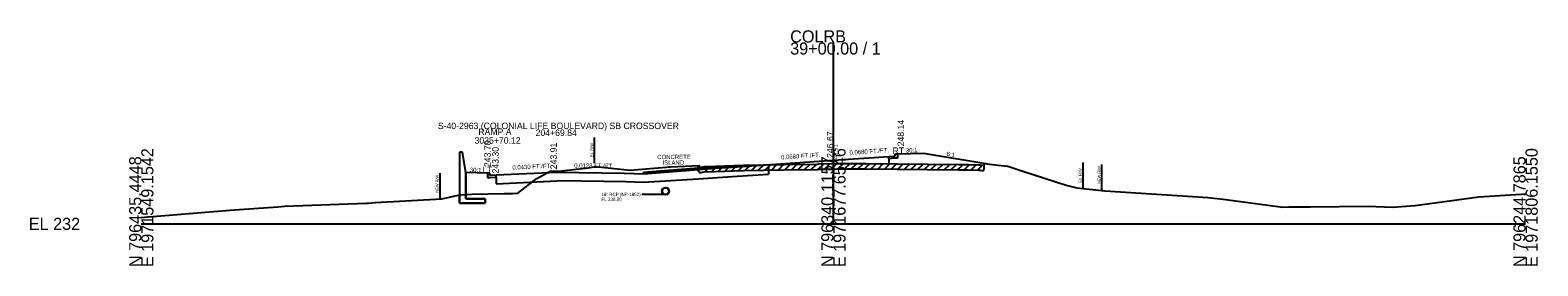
# Model space of a CAD drawing. Extents: x -26 to 1971766, y -10 to 796432.
# Drawn here: x -25.7 to 322.8, y 3490.3 to 3544.7 of the extents above; entities that cross this region are included whole.
import ezdxf

# ---------------------------------------------------------------- set-up
doc = ezdxf.new("R2010")
doc.units = 0
for name, color, linetype in [('BR_AUTO DIMENSION', 7, 'Continuous'), ('BR_BORDER LINES', 7, 'Continuous'), ('BR_CENTER LINE BASELINE', 7, 'Continuous'), ('BR_CONCRETE', 7, 'Continuous'), ('BR_DETAILS', 7, 'Continuous'), ('BR_PRESTRESSED BEAM', 7, 'Continuous'), ('BR_REBAR', 7, 'Continuous'), ('BR_TABLE LINES', 7, 'Continuous'), ('Default', 7, 'Continuous'), ('Level 31', 7, 'Continuous'), ('MISCELLANEOUS', 7, 'Continuous'), ('North Arrow', 7, 'Continuous'), ('RD_EX_Conc', 7, 'Continuous'), ('RD_EX_Road', 7, 'Continuous'), ('RD_HC_CL_Rel', 7, 'Continuous'), ('RD_PD_ALT2_TnTmp', 7, 'Continuous'), ('RD_PD_CstnLmt', 7, 'Continuous'), ('RD_PD_Final_LnLine', 7, 'Continuous'), ('RD_PD_Final_TrvlWay', 7, 'Continuous'), ('RD_PD_FOC', 7, 'Continuous'), ('RD_PD_MedBWall', 7, 'Continuous'), ('RD_PD_WallFill', 7, 'Continuous'), ('RD_SHT_IplotShp', 7, 'Continuous')]:
    doc.layers.add(name, color=color, linetype=linetype)

msp = doc.modelspace()

# ---------------------------------------------------------------- linework, layer by layer
at = {"layer": 'BR_AUTO DIMENSION'}
for p, q in [((160, 3500), (160, 3541.89)), ((0, 3500), (160, 3500)), ((160, 3500), (320, 3500))]:
    msp.add_line(p, q, dxfattribs=at)
at = {"layer": 'BR_BORDER LINES'}
msp.add_lwpolyline([(0, 3501.48), (1.51, 3501.6), (2.69, 3501.69), (20.49, 3503.18), (31.58, 3503.94), (33.11, 3504.06), (37.34, 3504.26), (52.05, 3504.8), (52.51, 3504.81), (54.04, 3504.9), (69.48, 3505.79), (72.25, 3506.42), (73.28, 3506.64), (73.59, 3506.68), (76.43, 3506.85), (83.89, 3507.03), (85.79, 3507.04), (87.02, 3507.11), (91.43, 3510.51), (94.55, 3512.13), (97.11, 3512.22), (103.34, 3512.97), (104.72, 3513.19), (105.7, 3513.13), (112.99, 3512.37), (121.3, 3513.12), (121.97, 3513.17), (122.37, 3513.18), (128.97, 3513.44), (129.07, 3513.04), (130.08, 3513.24), (132.75, 3513.34), (139.22, 3513.57), (148.63, 3513.7), (156.3, 3513.81), (156.6, 3513.87), (160, 3513.91), (161.43, 3513.92), (167.06, 3513.96), (167.58, 3513.94), (174.7, 3513.87), (181.71, 3513.8), (189.02, 3513.72), (190.37, 3513.71), (191.16, 3513.69), (193.57, 3513.65), (193.9, 3513.61), (194.7, 3513.5), (194.8, 3513.9), (198.77, 3513.48), (200.33, 3513.31), (203.78, 3512.2), (213.78, 3508.95), (216.24, 3508.3), (222.73, 3507.6), (240.69, 3506.49), (246.55, 3506.09), (250.08, 3505.69), (263.86, 3503.85), (265.31, 3503.91), (270.31, 3503.95), (283.62, 3504.05), (289.23, 3503.88), (294.46, 3504.21), (309.22, 3506.27), (318.95, 3506.84), (320, 3506.91)], dxfattribs=at)
at = {"layer": 'BR_CENTER LINE BASELINE'}
for p, q in [((128.75, 3512.18), (128.75, 3513.43)), ((194.79, 3513.84), (194.79, 3512.59)), ((128.75, 3512.18), (128.97, 3512.19)), ((128.97, 3512.19), (129.07, 3511.79)), ((129.07, 3511.79), (130.08, 3511.99)), ((130.08, 3511.99), (132.75, 3512.09)), ((132.75, 3512.09), (139.22, 3512.32)), ((139.22, 3512.32), (148.63, 3512.45)), ((148.63, 3512.45), (156.3, 3512.56)), ((156.3, 3512.56), (156.6, 3512.62)), ((156.6, 3512.62), (160, 3512.66)), ((160, 3512.66), (161.43, 3512.67)), ((161.43, 3512.67), (167.06, 3512.71)), ((167.06, 3512.71), (167.58, 3512.69)), ((167.58, 3512.69), (174.7, 3512.62)), ((174.7, 3512.62), (181.71, 3512.55)), ((181.71, 3512.55), (189.02, 3512.47)), ((189.02, 3512.47), (190.37, 3512.46)), ((190.37, 3512.46), (191.16, 3512.44)), ((191.16, 3512.44), (193.57, 3512.4)), ((193.57, 3512.4), (193.9, 3512.36)), ((193.9, 3512.36), (194.7, 3512.25)), ((194.7, 3512.25), (194.79, 3512.59))]:
    msp.add_line(p, q, dxfattribs=at)
at = {"layer": 'BR_DETAILS'}
for p, q in [((74.28, 3516.53), (73.53, 3516.53)), ((73.53, 3516.53), (73.53, 3504.75)), ((75.03, 3511.86), (74.28, 3516.53)), ((133.69, 3513.23), (116.06, 3511.86)), ((133.69, 3512.9), (133.69, 3513.23)), ((75.03, 3505.76), (75.03, 3511.86)), ((116.06, 3511.53), (133.69, 3512.9)), ((116.06, 3511.53), (116.06, 3511.86)), ((73.53, 3504.75), (75.03, 3504.75)), ((79.53, 3505.76), (75.03, 3505.76)), ((75.03, 3504.75), (79.53, 3504.76)), ((79.53, 3504.76), (79.53, 3505.76))]:
    msp.add_line(p, q, dxfattribs=at)
at = {"layer": 'BR_PRESTRESSED BEAM'}
for p, q in [((174.23, 3515.14), (172.81, 3515.05)), ((174.82, 3515.14), (174.23, 3515.14)), ((174.82, 3516.14), (174.82, 3515.14)), ((80.02, 3511.7), (80.02, 3510.7)), ((80.02, 3511.7), (80.02, 3510.7)), ((80.02, 3510.7), (80.61, 3510.7)), ((80.61, 3510.7), (82.03, 3510.78))]:
    msp.add_line(p, q, dxfattribs=at)
at = {"layer": 'BR_TABLE LINES'}
for p, q in [((104.72, 3519.98), (104.72, 3513.98)), ((217.62, 3514.16), (217.62, 3508.16))]:
    msp.add_line(p, q, dxfattribs=at)
at = {"layer": 'Level 31'}
for p, q in [((130.28, 3512), (131.61, 3513.29)), ((131.82, 3512.05), (133.15, 3513.35)), ((133.36, 3512.11), (134.69, 3513.41)), ((134.9, 3512.16), (136.23, 3513.46)), ((136.43, 3512.22), (137.76, 3513.52)), ((137.97, 3512.28), (139.3, 3513.57)), ((139.51, 3512.33), (140.81, 3513.59)), ((141.04, 3512.35), (142.34, 3513.62)), ((142.58, 3512.37), (143.88, 3513.64)), ((144.12, 3512.39), (145.42, 3513.66)), ((145.65, 3512.41), (146.95, 3513.68)), ((147.19, 3512.43), (148.49, 3513.7)), ((148.73, 3512.45), (150.03, 3513.72)), ((150.27, 3512.48), (151.57, 3513.74)), ((151.8, 3512.5), (153.1, 3513.77)), ((153.34, 3512.52), (154.64, 3513.79)), ((154.88, 3512.54), (156.18, 3513.81)), ((156.41, 3512.58), (157.75, 3513.88)), ((157.95, 3512.64), (159.24, 3513.9)), ((159.49, 3512.65), (160.78, 3513.91)), ((161.03, 3512.67), (162.32, 3513.93)), ((162.56, 3512.68), (163.85, 3513.94)), ((164.1, 3512.69), (165.39, 3513.95)), ((165.64, 3512.7), (166.93, 3513.96)), ((167.17, 3512.71), (168.43, 3513.93)), ((168.71, 3512.68), (169.98, 3513.91)), ((170.25, 3512.66), (171.52, 3513.9)), ((171.78, 3512.65), (173.05, 3513.89)), ((173.32, 3512.63), (174.59, 3513.87)), ((174.86, 3512.62), (176.13, 3513.86)), ((176.4, 3512.6), (177.66, 3513.84)), ((177.93, 3512.59), (179.2, 3513.82)), ((179.47, 3512.57), (180.74, 3513.81)), ((181.01, 3512.55), (182.27, 3513.79)), ((182.54, 3512.54), (183.81, 3513.78)), ((184.08, 3512.52), (185.35, 3513.76)), ((185.62, 3512.51), (186.89, 3513.74)), ((187.16, 3512.49), (188.42, 3513.73)), ((188.69, 3512.48), (189.96, 3513.71)), ((190.23, 3512.46), (191.48, 3513.68)), ((191.77, 3512.43), (193.03, 3513.66)), ((193.3, 3512.41), (194.46, 3513.54)), ((128.75, 3512.18), (129.76, 3513.18))]:
    msp.add_line(p, q, dxfattribs=at)
at = {"layer": 'MISCELLANEOUS'}
for p, q in [((144.96, 3513.65), (148.63, 3513.7)), ((148.63, 3513.7), (156.3, 3513.81)), ((156.3, 3513.81), (156.6, 3513.87)), ((156.6, 3513.87), (160, 3513.91)), ((160, 3513.91), (161.43, 3513.92)), ((161.43, 3513.92), (167.06, 3513.96)), ((167.06, 3513.96), (167.58, 3513.94)), ((167.58, 3513.94), (172.81, 3513.89))]:
    msp.add_line(p, q, dxfattribs=at)
at = {"layer": 'North Arrow'}
for p, q in [((137.72, 3513.16), (160, 3514.67)), ((160, 3514.67), (172.81, 3515.55)), ((82.03, 3511.3), (96.07, 3511.91)), ((96.07, 3511.91), (111.61, 3511.71))]:
    msp.add_line(p, q, dxfattribs=at)
at = {"layer": 'RD_EX_Conc'}
for p, q in [((172.81, 3515.55), (174.23, 3515.64)), ((172.81, 3515.57), (172.81, 3515.55)), ((174.23, 3515.64), (174.32, 3516.14)), ((174.32, 3516.14), (174.82, 3516.14)), ((80.52, 3511.7), (80.02, 3511.7)), ((80.52, 3511.7), (80.02, 3511.7)), ((80.61, 3511.2), (80.52, 3511.7)), ((80.61, 3511.2), (80.52, 3511.7)), ((82.03, 3511.28), (80.61, 3511.2)), ((82.03, 3511.3), (82.03, 3511.28))]:
    msp.add_line(p, q, dxfattribs=at)
at = {"layer": 'RD_EX_Road'}
for p, q in [((144.96, 3513.65), (144.96, 3511.49)), ((172.81, 3515.55), (172.81, 3515.57)), ((172.81, 3515.05), (172.81, 3515.55)), ((172.81, 3515.05), (172.81, 3513.89)), ((82.03, 3511.28), (82.03, 3511.3)), ((82.03, 3510.78), (82.03, 3511.28)), ((82.03, 3510.78), (82.03, 3509.26)), ((82.03, 3509.26), (96.04, 3509.97)), ((96.04, 3509.97), (96.53, 3510)), ((96.53, 3510), (112.06, 3509.8)), ((112.06, 3509.8), (116.06, 3509.64)), ((116.06, 3509.64), (128.75, 3510.42)), ((128.75, 3510.42), (137.72, 3510.99)), ((137.72, 3510.99), (144.96, 3511.49))]:
    msp.add_line(p, q, dxfattribs=at)
at = {"layer": 'RD_PD_CstnLmt'}
for p, q in [((221.99, 3513.68), (221.99, 3507.68)), ((68.99, 3511.68), (68.99, 3505.68))]:
    msp.add_line(p, q, dxfattribs=at)
at = {"layer": 'RD_PD_Final_LnLine'}
for p, q in [((174.82, 3516.14), (180.82, 3516.34)), ((180.82, 3516.34), (196.58, 3513.71)), ((75.03, 3511.86), (75.03, 3505.76)), ((75.03, 3510.78), (75.03, 3509.24)), ((73.53, 3504.75), (73.53, 3506.67)), ((75.03, 3504.75), (73.53, 3504.75)), ((75.03, 3505.76), (79.53, 3505.76)), ((79.53, 3504.76), (75.03, 3504.75)), ((79.53, 3505.76), (79.53, 3504.76))]:
    msp.add_line(p, q, dxfattribs=at)
at = {"layer": 'RD_PD_FOC'}
msp.add_line((120.7, 3506.8), (115.7, 3506.8), dxfattribs=at)
for radius in [0.85, 0.75]:
    msp.add_circle((121.2, 3507.55), radius, dxfattribs=at)
at = {"layer": 'RD_PD_MedBWall'}
for p, q in [((80.02, 3511.7), (75.03, 3511.86)), ((111.61, 3511.71), (116.06, 3511.53)), ((133.69, 3512.9), (137.72, 3513.16))]:
    msp.add_line(p, q, dxfattribs=at)

# ---------------------------------------------------------------- texts
at = {"layer": 'BR_AUTO DIMENSION'}
for s, p in [('COLRB', (150, 3541.89)), ('39+00.00 / 1', (150, 3539.09)), ('EL 232', (-26, 3498.6))]:
    msp.add_text(s, height=2.8, dxfattribs=at).set_placement(p)
for s, p in [('E 1971549.1542', (2.8, 3490)), ('E 1971677.6546', (162.8, 3490)), ('E 1971806.1550', (322.8, 3490)), ('N 796435.4448', (0, 3490)), ('N 796340.1157', (160, 3490)), ('N 796244.7865', (320, 3490))]:
    msp.add_text(s, height=2.8, rotation=90, dxfattribs=at).set_placement(p)
at = {"layer": 'BR_CONCRETE'}
for s, rotation, p in [('0.0680 FT./FT.', 3.8901, (163.75, 3515.93)), ('30:1', 1.9092, (176.75, 3516.46)), ('0.0430 FT./FT.', 2.9008, (85.8, 3512.49)), ('0.0128 FT./FT.', 359.2656, (100.07, 3512.99)), ('0.0680 FT./FT.', 3.8864, (147.92, 3514.86)), ('6:1', 350.5377, (186.11, 3515.71)), ('30:1', 358.8542, (75.94, 3511.98))]:
    msp.add_text(s, height=1, rotation=rotation, dxfattribs=at).set_placement(p)
at = {"layer": 'BR_REBAR'}
for s, p in [('RT', (173.67, 3516.14)), ('LT', (78.82, 3511.7))]:
    msp.add_text(s, height=1.5, dxfattribs=at).set_placement(p)
at = {"layer": 'BR_TABLE LINES'}
for p in [(104.47, 3515.36), (217.37, 3509.54)]:
    msp.add_text('Ex. R/W ', height=0.65, rotation=90, dxfattribs=at).set_placement(p)
at = {"layer": 'Default'}
msp.add_text('243.70', height=1.5, rotation=90, dxfattribs=at).set_placement((80.77, 3513.11))
at = {"layer": 'RD_HC_CL_Rel'}
for s, p in [(' 246.67', (160, 3514.67)), (' 243.30', (82.61, 3511.07)), (' 243.91', (96.06, 3512.04))]:
    msp.add_text(s, height=1.5, rotation=90, dxfattribs=at).set_placement(p)
at = {"layer": 'RD_PD_ALT2_TnTmp'}
for s, p in [('CONCRETE', (119.27, 3514.95)), ('ISLAND', (120.49, 3513.64))]:
    msp.add_text(s, height=0.999, dxfattribs=at).set_placement(p)
at = {"layer": 'RD_PD_CstnLmt'}
for p in [(68.72, 3507.24), (221.73, 3509.24)]:
    msp.add_text('NEW R/W ', height=0.65, rotation=90, dxfattribs=at).set_placement(p)
at = {"layer": 'RD_PD_Final_TrvlWay'}
msp.add_text('248.14', height=1.5, rotation=90, dxfattribs=at).set_placement((176.32, 3517.89))
at = {"layer": 'RD_PD_FOC'}
for s, p in [('18" RCP (NP-1852)', (106.37, 3506.42)), ('FL 238.80', (106.37, 3505.3))]:
    msp.add_text(s, height=0.75, dxfattribs=at).set_placement(p)
at = {"layer": 'RD_PD_WallFill'}
for s, p in [('S-40-2963 (COLONIAL LIFE BOULEVARD) SB CROSSOVER', (68.55, 3521.88)), ('RAMP A', (77.91, 3520.51)), ('204+69.84', (91.15, 3520.29)), ('3035+70.12', (77.04, 3518.51))]:
    msp.add_text(s, height=1.5, dxfattribs=at).set_placement(p)
at = {"layer": 'RD_SHT_IplotShp'}
msp.add_text('245.91', height=1, rotation=90, dxfattribs=at).set_placement((161, 3514.16))

doc.saveas('drawing.dxf')
